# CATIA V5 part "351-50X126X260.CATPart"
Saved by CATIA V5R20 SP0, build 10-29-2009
Part number: 351-50X126X260
Definition: NONE
Nomenclature: 351-50X126X260
Source: Unknown
Description: 351-50X126X260
Bounding box of the stored display mesh (mm): x -10 to 250, y -32.5 to 32.5, z -32.5 to 32.5
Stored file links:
  C:\Users\Utente\Desktop\IO LAVORO\3D X SITO CF\X SITO\PLASTICA\351\351-50X126X260.CATPart
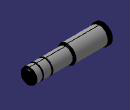
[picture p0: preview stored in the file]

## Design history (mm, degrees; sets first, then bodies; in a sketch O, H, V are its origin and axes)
Body1 "351-50X126X260" (main body)
  Solid1: solid without history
